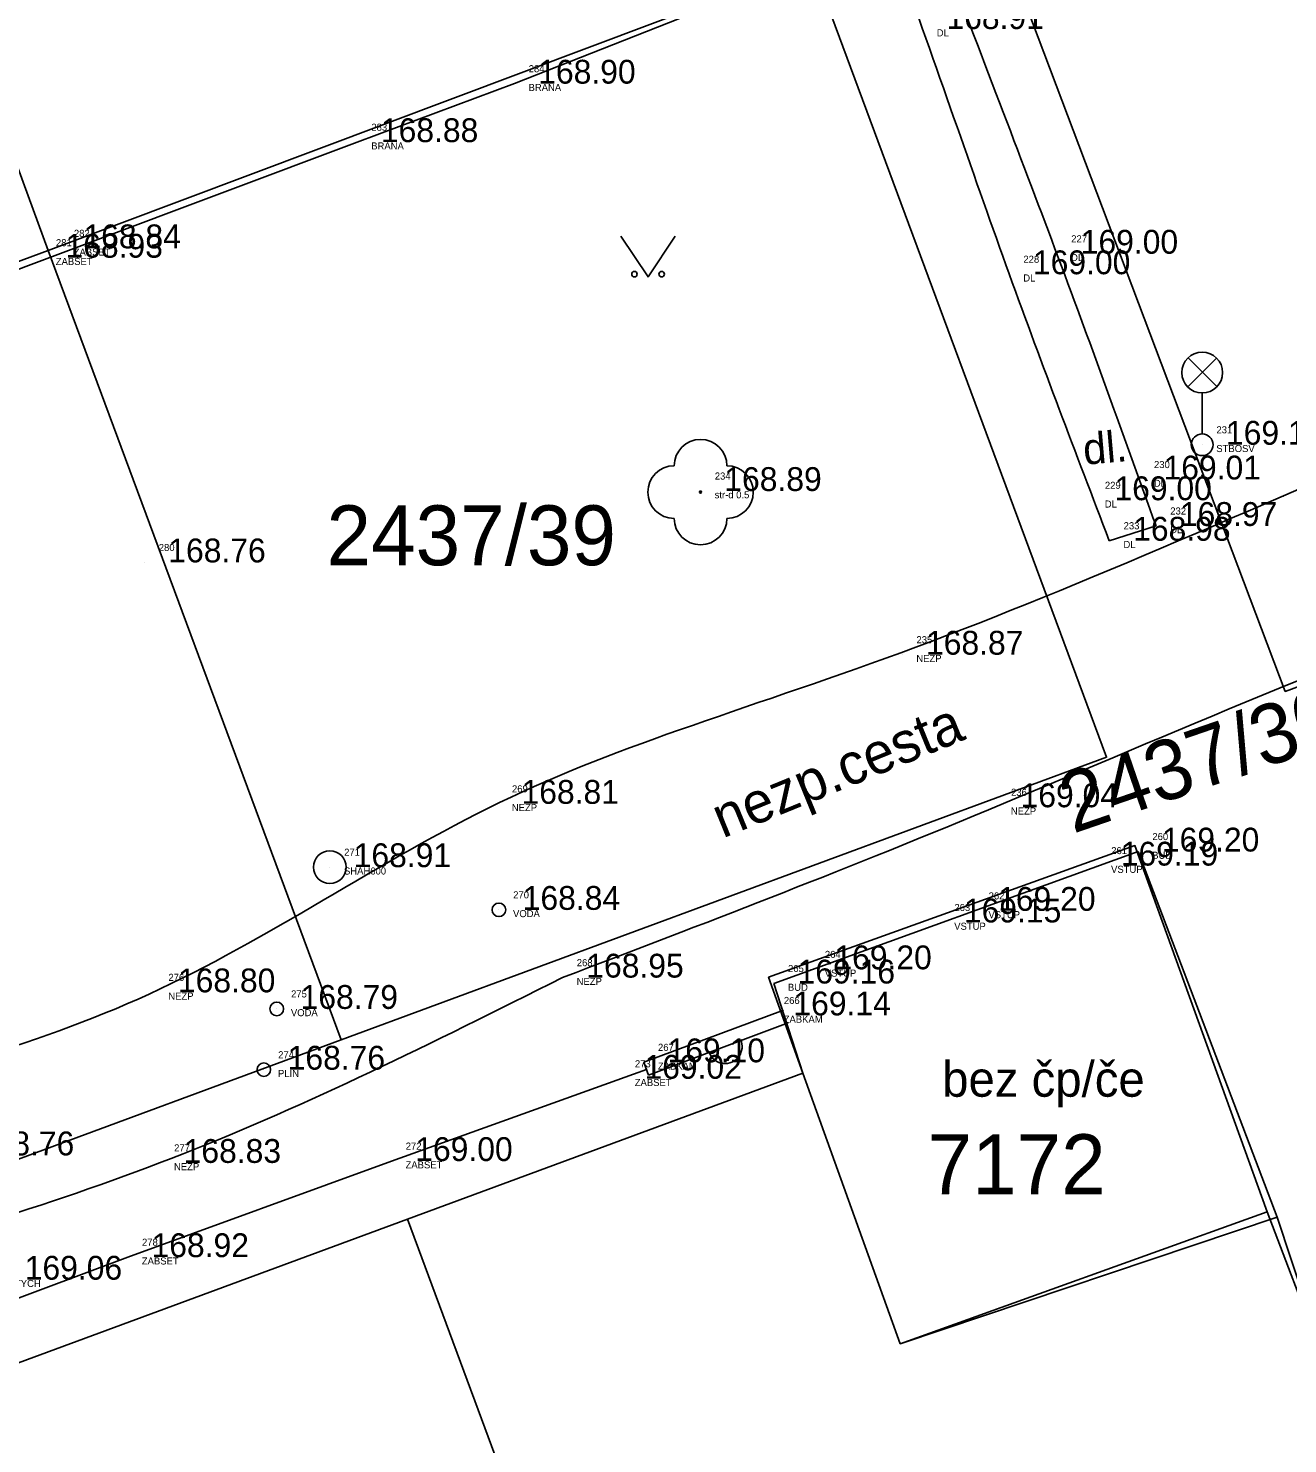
# Model space of a CAD drawing. Extents: x -566117 to -565580, y -1202428 to -1201938.
# Drawn here: x -566016.98 to -565993.84, y -1202154.53 to -1202128.54 of the extents above; entities that cross this region are included whole.
import ezdxf

# ---------------------------------------------------------------- set-up
doc = ezdxf.new("R2010")
doc.units = 0
for name, color, linetype in [('Bod', 7, 'Continuous'), ('BUDOVY_MĚŘ (Construction)', 7, 'Continuous'), ('BUOVY_NEMĚŘ', 7, 'Continuous'), ('CIZÍ_NADZEM', 7, 'Continuous'), ('Implicitní', 7, 'Continuous'), ('Kanalizace', 7, 'Continuous'), ('Katastr', 7, 'Continuous'), ('Kod', 7, 'Continuous'), ('Oplocení', 7, 'Continuous'), ('Plin', 7, 'Continuous'), ('POMOC_POPIS', 7, 'Continuous'), ('Voda', 7, 'Continuous'), ('Výška', 7, 'Continuous'), ('ZELEŇ', 7, 'Continuous'), ('ZN_KULTUR', 7, 'Continuous'), ('Zpevněné plohy', 7, 'Continuous'), ('Číslo', 7, 'Continuous'), ('Číslo popisné', 7, 'Continuous')]:
    doc.layers.add(name, color=color, linetype=linetype)

# ---------------------------------------------------------------- blocks, each defined once
blk = doc.blocks.new('A$C69D74C1E')
at = {"layer": 'Katastr'}
for p, q in [((48.32, -64.18), (45.45, -56.39)), ((62.35, -58.91), (48.32, -64.18)), ((48.32, -64.18), (40.46, -67.08)), ((53.7, -78.68), (48.32, -64.18)), ((39.59, -83.89), (53.7, -78.68)), ((54.92, -81.97), (62.18, -79.29)), ((70.71, -81.84), (77.39, -99.44)), ((45.14, -85.58), (54.92, -81.97)), ((54.92, -81.97), (58.32, -91.15))]:
    blk.add_line(p, q, dxfattribs=at)
for points in [[(65.53, -57.69), (71.04, -72.28), (85.1, -67.09)], [(53.7, -78.68), (67.76, -73.49), (62.35, -58.91)], [(70.71, -81.84), (68.28, -75.11), (61.55, -77.53), (62.18, -79.29)], [(70.71, -81.84), (63.97, -84.26), (62.18, -79.29)]]:
    blk.add_lwpolyline(points, dxfattribs=at)
for s, p in [('2437/39', (53.43, -69.963)), ('7172', (64.47, -81.513))]:
    blk.add_text(s, height=1.1, dxfattribs=at).set_placement(p)
blk.add_text('2437/307', height=1.1, rotation=19, dxfattribs=at).set_placement((67.14, -74.896))
blk = doc.blocks.new('6.560')
at = {"layer": 'CIZÍ_NADZEM'}
for p, q in [((-0.528, 2.124), (0.528, 3.18)), ((0.544, 2.13), (-0.512, 3.188)), ((0, 1.9), (0, 0.4))]:
    blk.add_line(p, q, dxfattribs=at)
for centre, radius in [((0, 2.65), 0.75), ((0, 0), 0.4)]:
    blk.add_circle(centre, radius, dxfattribs=at)
blk = doc.blocks.new('POINT_DISPLAY')
at = {"layer": 'Implicitní'}
blk.add_line((0, 0), (0, 0), dxfattribs=at)
blk = doc.blocks.new('3$13')
at = {"layer": 'ZELEŇ'}
blk.add_circle((0, 0), 0.02, dxfattribs=at)
for centre, start, end in [((0.000055, 0.484), 0, 179.9999972), ((-0.483945, 0), 90, 269.9999972), ((0.484055, 0), 270, 89.9999972), ((0.000055, -0.484), 180.0000028, 0)]:
    blk.add_arc(centre, 0.484, start, end, dxfattribs=at)
blk.add_blockref('POINT_DISPLAY', (0, 0), dxfattribs=at)
blk = doc.blocks.new('3.140_2')
at = {"layer": 'ZN_KULTUR'}
blk.add_lwpolyline([(-1, 1.5), (0, 0), (1, 1.5)], dxfattribs=at)
for centre in [(-0.5, 0.1), (0.5, 0.1)]:
    blk.add_circle(centre, 0.1, dxfattribs=at)

msp = doc.modelspace()

# ---------------------------------------------------------------- linework, layer by layer
at = {"layer": 'BUDOVY_MĚŘ (Construction)'}
for p, q in [((-566003.285, -1202146.084), (-565996.593, -1202143.66)), ((-565996.593, -1202143.66), (-565994.039, -1202150.374)), ((-566003.285, -1202146.084), (-566002.75, -1202147.73))]:
    msp.add_line(p, q, dxfattribs=at)
at = {"layer": 'BUOVY_NEMĚŘ'}
msp.add_lwpolyline([(-566002.75, -1202147.73), (-566000.96, -1202152.7), (-565994.039, -1202150.374)], dxfattribs=at)
at = {"layer": 'Kanalizace'}
msp.add_circle((-566011.439, -1202143.947), 0.3, dxfattribs=at)
at = {"layer": 'Oplocení'}
for p, q in [((-566010.938, -1202130.632), (-566008.048, -1202129.558)), ((-566005.673, -1202147.531), (-566003.107, -1202146.574)), ((-566005.586, -1202147.765), (-566003.02, -1202146.809)), ((-566005.673, -1202147.531), (-566005.586, -1202147.765)), ((-566005.623, -1202147.665), (-566010.308, -1202149.344)), ((-566010.308, -1202149.344), (-566015.152, -1202151.109)), ((-565993.254, -1202152.755), (-565994.039, -1202150.374)), ((-566015.152, -1202151.109), (-566020.196, -1202152.99))]:
    msp.add_line(p, q, dxfattribs=at)
for points in [[(-566008.048, -1202129.558), (-566002.019, -1202127.175), (-566011.366, -1202101.546), (-566011.958, -1202101.817)], [(-566030.536, -1202137.986), (-566010.938, -1202130.632)]]:
    msp.add_lwpolyline(points, dxfattribs=at)
msp.add_arc((-566004.179, -1202147.241), 0.313, 202.9937, 24.1153, dxfattribs=at)
at = {"layer": 'Plin'}
msp.add_circle((-566012.651, -1202147.666), 0.125, dxfattribs=at)
at = {"layer": 'Voda'}
for centre in [(-566008.334, -1202144.731), (-566012.414, -1202146.55)]:
    msp.add_circle(centre, 0.125, dxfattribs=at)
at = {"layer": 'Zpevněné plohy'}
msp.add_line((-565997.121, -1202137.952), (-565996.263, -1202137.681), dxfattribs=at)
for points in [[(-566009.948, -1202100.608), (-566009.407, -1202102.066), (-566008.304, -1202105.035), (-566006.79, -1202109.193), (-566004.944, -1202114.533), (-566002.561, -1202120.799), (-566000.13, -1202127.337), (-565997.98, -1202132.903), (-565996.863, -1202136.011), (-565996.263, -1202137.681)], [(-565997.121, -1202137.952), (-565997.744, -1202136.324), (-565998.938, -1202133.21), (-566000.87, -1202127.568), (-566003.339, -1202120.977), (-566005.858, -1202114.752), (-566007.678, -1202109.538), (-566009.197, -1202105.454), (-566010.206, -1202102.534), (-566010.746, -1202100.971)], [(-565996.343, -1202250.678), (-565998.087, -1202246.935), (-566000.423, -1202241.92), (-566004.309, -1202234.328), (-566007.075, -1202227.602), (-566010.343, -1202219.887), (-566012.893, -1202211.917), (-566015.796, -1202204.301), (-566017.921, -1202196.368), (-566020.346, -1202187.744), (-566022.925, -1202178.898), (-566025.07, -1202169.591), (-566028.365, -1202159.949), (-566030.289, -1202151.119), (-566033.484, -1202142.933), (-566036.408, -1202135.565), (-566040.083, -1202126.773), (-566044.556, -1202117.939), (-566046.435, -1202111.858), (-566047.33, -1202108.96)], [(-566021.285, -1202148.373), (-566019.023, -1202147.793), (-566014.418, -1202146.612), (-566008.323, -1202142.269), (-566000.952, -1202140.271), (-565990.236, -1202135.453), (-565980.027, -1202131.426), (-565971.991, -1202128.888), (-565970.232, -1202128.332)], [(-565970.847, -1202132.15), (-565972.12, -1202132.672), (-565979.637, -1202135.754), (-565989.362, -1202138.602), (-565999.98, -1202143.234), (-566004.496, -1202144.957), (-566007.165, -1202145.975)], [(-566021.002, -1202151.454), (-566018.833, -1202150.819), (-566014.054, -1202149.419), (-566009.599, -1202147.192), (-566007.165, -1202145.975)]]:
    msp.add_open_spline(points, degree=3, dxfattribs=at)

# ---------------------------------------------------------------- block references
at = {"layer": 'Bod'}
for p in [(-566000.55, -1202128.555), (-566008.048, -1202129.558), (-566010.938, -1202130.632), (-566016.733, -1202132.754), (-566016.402, -1202132.582), (-565998.083, -1202132.681), (-565998.961, -1202133.058), (-565995.415, -1202136.189), (-565996.562, -1202136.827), (-566004.63, -1202137.039), (-565993.921, -1202137.146), (-565997.464, -1202137.208), (-565996.263, -1202137.681), (-565997.121, -1202137.952), (-566014.843, -1202138.35), (-566000.926, -1202140.045), (-566008.355, -1202142.784), (-565999.188, -1202142.847), (-565996.593, -1202143.66), (-565997.348, -1202143.918), (-566011.439, -1202143.947), (-566008.334, -1202144.731), (-566000.23, -1202144.962), (-565999.601, -1202144.749), (-566007.165, -1202145.975), (-566002.608, -1202145.823), (-566014.667, -1202146.246), (-566003.285, -1202146.084), (-566012.414, -1202146.55), (-566003.362, -1202146.669), (-566005.673, -1202147.531), (-566012.651, -1202147.666), (-566006.098, -1202147.833), (-566014.562, -1202149.378), (-566010.308, -1202149.344), (-565994.039, -1202150.374), (-566015.152, -1202151.109)]:
    msp.add_blockref('POINT_DISPLAY', p, dxfattribs=at)
at = {"layer": 'CIZÍ_NADZEM', "xscale": 0.5, "yscale": 0.5}
msp.add_blockref('6.560', (-565995.415, -1202136.189), dxfattribs=at)
at = {"layer": 'Implicitní'}
msp.add_blockref('A$C69D74C1E', (-566064.93, -1202068.44), dxfattribs=at)
at = {"layer": 'ZELEŇ'}
msp.add_blockref('3$13', (-566004.63, -1202137.059), dxfattribs=at)
at = {"layer": 'ZN_KULTUR', "xscale": 0.5, "yscale": 0.5}
msp.add_blockref('3.140_2', (-566005.593, -1202133.107), dxfattribs=at)

# ---------------------------------------------------------------- texts
at = {"layer": 'Kod'}
for s, p in [('DL', (-566000.291, -1202128.69)), ('BRANA', (-566007.789, -1202129.693)), ('BRANA', (-566010.679, -1202130.767)), ('ZABSET', (-566016.473, -1202132.888)), ('ZABSET', (-566016.143, -1202132.716)), ('DL', (-565997.824, -1202132.816)), ('DL', (-565998.702, -1202133.192)), ('STBOSV', (-565995.156, -1202136.324)), ('DL', (-565996.303, -1202136.962)), ('str-d 0.5', (-566004.371, -1202137.173)), ('DL', (-565997.205, -1202137.343)), ('DL', (-565996.003, -1202137.815)), ('DL', (-565996.861, -1202138.086)), ('NEZP', (-566000.666, -1202140.179)), ('NEZP', (-566008.096, -1202142.918)), ('NEZP', (-565998.929, -1202142.981)), ('BUD', (-565996.333, -1202143.794)), ('VSTUP', (-565997.089, -1202144.052)), ('SHAH600', (-566011.179, -1202144.082)), ('VODA', (-566008.074, -1202144.865)), ('VSTUP', (-565999.97, -1202145.097)), ('VSTUP', (-565999.341, -1202144.884)), ('NEZP', (-566006.906, -1202146.11)), ('VSTUP', (-566002.349, -1202145.958)), ('NEZP', (-566014.407, -1202146.38)), ('BUD', (-566003.025, -1202146.218)), ('VODA', (-566012.154, -1202146.684)), ('ZABKAM', (-566003.102, -1202146.804)), ('ZABKAM', (-566005.413, -1202147.665)), ('PLIN', (-566012.391, -1202147.801)), ('ZABSET', (-566005.838, -1202147.967)), ('NEZP', (-566014.302, -1202149.512)), ('ZABSET', (-566010.048, -1202149.479)), ('ZABSET', (-566014.892, -1202151.244)), ('TYCH', (-566017.222, -1202151.657))]:
    msp.add_text(s, height=0.13, dxfattribs=at).set_placement(p)
at = {"layer": 'POMOC_POPIS'}
for s, height, rotation, p in [('dl.', 0.57, 4.9059, (-565997.579, -1202136.558)), ('nezp.cesta', 0.75, 22.216, (-566004.225, -1202143.423))]:
    msp.add_text(s, height=height, rotation=rotation, dxfattribs=at).set_placement(p)
at = {"layer": 'Výška'}
for s, p in [('168.91', (-566000.113, -1202128.555)), ('168.90', (-566007.611, -1202129.558)), ('168.88', (-566010.501, -1202130.632)), ('168.84', (-566015.965, -1202132.582)), ('169.00', (-565997.646, -1202132.681)), ('168.93', (-566016.295, -1202132.754)), ('169.00', (-565998.524, -1202133.058)), ('169.11', (-565994.978, -1202136.189)), ('169.01', (-565996.125, -1202136.827)), ('168.89', (-566004.193, -1202137.039)), ('169.00', (-565997.027, -1202137.208)), ('168.97', (-565995.825, -1202137.681)), ('168.98', (-565996.683, -1202137.952)), ('168.76', (-566014.406, -1202138.35)), ('168.87', (-566000.488, -1202140.045)), ('168.81', (-566007.918, -1202142.784)), ('169.04', (-565998.751, -1202142.847)), ('169.20', (-565996.155, -1202143.66)), ('168.91', (-566011.001, -1202143.947)), ('169.19', (-565996.911, -1202143.918)), ('168.84', (-566007.896, -1202144.731)), ('169.20', (-565999.163, -1202144.749)), ('169.15', (-565999.792, -1202144.962)), ('169.20', (-566002.171, -1202145.823)), ('168.95', (-566006.728, -1202145.975)), ('169.16', (-566002.847, -1202146.084)), ('168.80', (-566014.229, -1202146.246)), ('168.79', (-566011.976, -1202146.55)), ('169.14', (-566002.924, -1202146.669)), ('168.76', (-566012.213, -1202147.666)), ('169.10', (-566005.235, -1202147.531)), ('169.02', (-566005.66, -1202147.833)), ('168.76', (-566017.923, -1202149.24)), ('168.83', (-566014.124, -1202149.378)), ('169.00', (-566009.87, -1202149.344)), ('168.92', (-566014.714, -1202151.109)), ('169.06', (-566017.043, -1202151.523))]:
    msp.add_text(s, height=0.4375, dxfattribs=at).set_placement(p)
at = {"layer": 'Číslo'}
for s, p in [('284', (-566007.786, -1202129.349)), ('283', (-566010.676, -1202130.423)), ('282', (-566016.14, -1202132.372)), ('281', (-566016.47, -1202132.544)), ('227', (-565997.821, -1202132.472)), ('228', (-565998.699, -1202132.848)), ('231', (-565995.153, -1202135.98)), ('230', (-565996.3, -1202136.618)), ('234', (-566004.368, -1202136.829)), ('229', (-565997.202, -1202136.999)), ('232', (-565996.001, -1202137.471)), ('233', (-565996.858, -1202137.742)), ('280', (-566014.581, -1202138.141)), ('235', (-566000.663, -1202139.835)), ('269', (-566008.093, -1202142.574)), ('236', (-565998.926, -1202142.637)), ('260', (-565996.33, -1202143.45)), ('271', (-566011.176, -1202143.738)), ('261', (-565997.086, -1202143.708)), ('270', (-566008.071, -1202144.521)), ('262', (-565999.338, -1202144.54)), ('263', (-565999.967, -1202144.753)), ('264', (-566002.346, -1202145.614)), ('268', (-566006.903, -1202145.766)), ('265', (-566003.023, -1202145.874)), ('276', (-566014.404, -1202146.036)), ('275', (-566012.151, -1202146.34)), ('266', (-566003.099, -1202146.46)), ('267', (-566005.411, -1202147.321)), ('274', (-566012.388, -1202147.457)), ('273', (-566005.835, -1202147.623)), ('277', (-566014.299, -1202149.168)), ('272', (-566010.045, -1202149.135)), ('278', (-566014.889, -1202150.9))]:
    msp.add_text(s, height=0.13, dxfattribs=at).set_placement(p)
at = {"layer": 'Číslo popisné'}
msp.add_text('bez čp/če', height=0.65, dxfattribs=at).set_placement((-566000.191, -1202148.163))

doc.saveas('drawing.dxf')
